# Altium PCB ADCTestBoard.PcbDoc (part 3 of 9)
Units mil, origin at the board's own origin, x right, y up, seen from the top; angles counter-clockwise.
Board outline 11022.62 x 9187 mil, 8 copper layers (TopLayer, InternalPlane1, InternalPlane2, InternalPlane3, InternalPlane4, InternalPlane5, MidLayer1, BottomLayer), stack 103.8 mil thick; 1282 components, 637 nets, 4473 pads, 1306 vias.
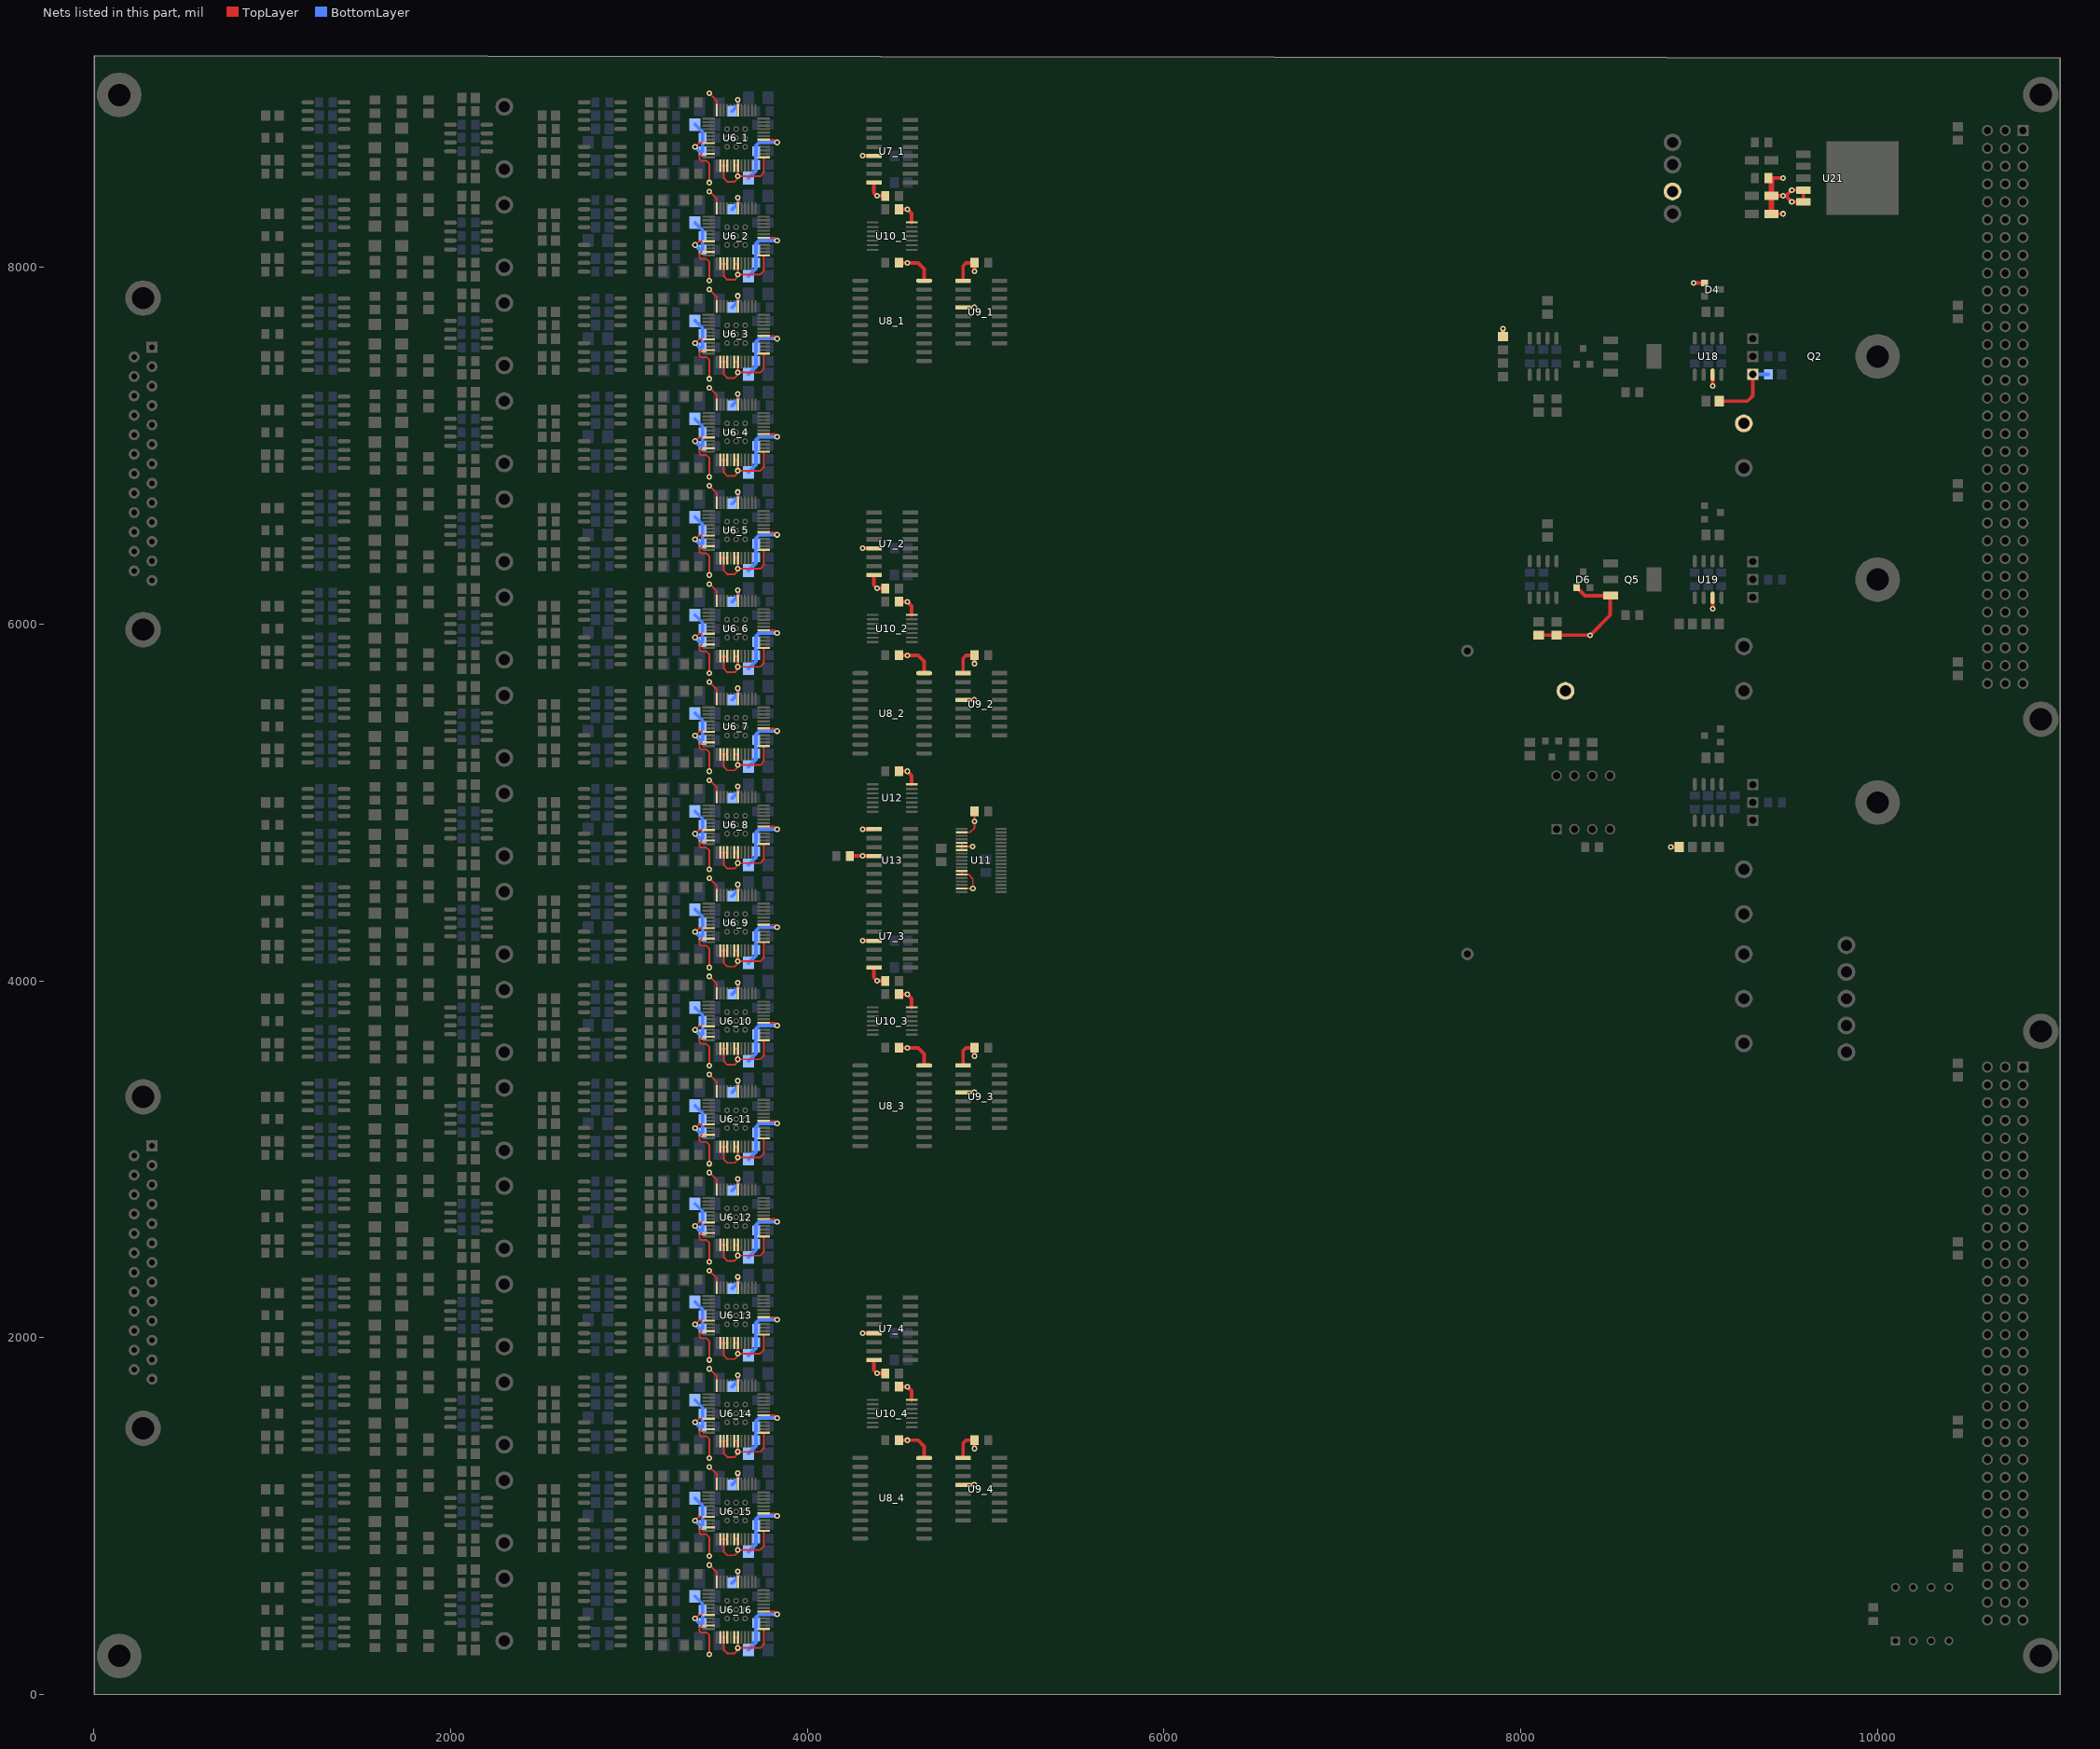
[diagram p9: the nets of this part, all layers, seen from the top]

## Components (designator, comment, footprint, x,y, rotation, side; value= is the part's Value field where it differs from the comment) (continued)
U3_10 "AD829JR" R-8D_N 2100,3775 r0 top (schematic designator U3)
U3_11 "AD829JR" R-8D_N 2100,3225 r0 top (schematic designator U3)
U3_12 "AD829JR" R-8D_N 2100,2675 r0 top (schematic designator U3)
U3_13 "AD829JR" R-8D_N 2100,2125 r0 top (schematic designator U3)
U3_14 "AD829JR" R-8D_N 2100,1575 r0 top (schematic designator U3)
U3_15 "AD829JR" R-8D_N 2100,1025 r0 top (schematic designator U3)
U3_16 "AD829JR" R-8D_N 2100,475 r0 top (schematic designator U3)
U4_1 "AD829JR" R-8D_N 2850,8600 r0 top (schematic designator U4)
U4_2 "AD829JR" R-8D_N 2850,8050 r0 top (schematic designator U4)
U4_3 "AD829JR" R-8D_N 2850,7500 r0 top (schematic designator U4)
U4_4 "AD829JR" R-8D_N 2850,6950 r0 top (schematic designator U4)
U4_5 "AD829JR" R-8D_N 2850,6400 r0 top (schematic designator U4)
U4_6 "AD829JR" R-8D_N 2850,5850 r0 top (schematic designator U4)
U4_7 "AD829JR" R-8D_N 2850,5300 r0 top (schematic designator U4)
U4_8 "AD829JR" R-8D_N 2850,4750 r0 top (schematic designator U4)
U4_9 "AD829JR" R-8D_N 2850,4200 r0 top (schematic designator U4)
U4_10 "AD829JR" R-8D_N 2850,3650 r0 top (schematic designator U4)
U4_11 "AD829JR" R-8D_N 2850,3100 r0 top (schematic designator U4)
U4_12 "AD829JR" R-8D_N 2850,2550 r0 top (schematic designator U4)
U4_13 "AD829JR" R-8D_N 2850,2000 r0 top (schematic designator U4)
U4_14 "AD829JR" R-8D_N 2850,1450 r0 top (schematic designator U4)
U4_15 "AD829JR" R-8D_N 2850,900 r0 top (schematic designator U4)
U4_16 "AD829JR" R-8D_N 2850,350 r0 top (schematic designator U4)
U5_1 "AD829JR" R-8D_N 2850,8850 r0 top (schematic designator U5)
U5_2 "AD829JR" R-8D_N 2850,8300 r0 top (schematic designator U5)
U5_3 "AD829JR" R-8D_N 2850,7750 r0 top (schematic designator U5)
U5_4 "AD829JR" R-8D_N 2850,7200 r0 top (schematic designator U5)
U5_5 "AD829JR" R-8D_N 2850,6650 r0 top (schematic designator U5)
U5_6 "AD829JR" R-8D_N 2850,6100 r0 top (schematic designator U5)
U5_7 "AD829JR" R-8D_N 2850,5550 r0 top (schematic designator U5)
U5_8 "AD829JR" R-8D_N 2850,5000 r0 top (schematic designator U5)
U5_9 "AD829JR" R-8D_N 2850,4450 r0 top (schematic designator U5)
U5_10 "AD829JR" R-8D_N 2850,3900 r0 top (schematic designator U5)
U5_11 "AD829JR" R-8D_N 2850,3350 r0 top (schematic designator U5)
U5_12 "AD829JR" R-8D_N 2850,2800 r0 top (schematic designator U5)
U5_13 "AD829JR" R-8D_N 2850,2250 r0 top (schematic designator U5)
U5_14 "AD829JR" R-8D_N 2850,1700 r0 top (schematic designator U5)
U5_15 "AD829JR" R-8D_N 2850,1150 r0 top (schematic designator U5)
U5_16 "AD829JR" R-8D_N 2850,600 r0 top (schematic designator U5)
U6_1 "AD7634" LFCSP_VQ48 3600,8725 r0 top (schematic designator U6)
U6_2 "AD7634" LFCSP_VQ48 3600,8175 r0 top (schematic designator U6)
U6_3 "AD7634" LFCSP_VQ48 3600,7625 r0 top (schematic designator U6)
U6_4 "AD7634" LFCSP_VQ48 3600,7075 r0 top (schematic designator U6)
U6_5 "AD7634" LFCSP_VQ48 3600,6525 r0 top (schematic designator U6)
U6_6 "AD7634" LFCSP_VQ48 3600,5975 r0 top (schematic designator U6)
U6_7 "AD7634" LFCSP_VQ48 3600,5425 r0 top (schematic designator U6)
U6_8 "AD7634" LFCSP_VQ48 3600,4875 r0 top (schematic designator U6)
U6_9 "AD7634" LFCSP_VQ48 3600,4325 r0 top (schematic designator U6)
U6_10 "AD7634" LFCSP_VQ48 3600,3775 r0 top (schematic designator U6)
U6_11 "AD7634" LFCSP_VQ48 3600,3225 r0 top (schematic designator U6)
U6_12 "AD7634" LFCSP_VQ48 3600,2675 r0 top (schematic designator U6)
U6_13 "AD7634" LFCSP_VQ48 3600,2125 r0 top (schematic designator U6)
U6_14 "AD7634" LFCSP_VQ48 3600,1575 r0 top (schematic designator U6)
U6_15 "AD7634" LFCSP_VQ48 3600,1025 r0 top (schematic designator U6)
U6_16 "AD7634" LFCSP_VQ48 3600,475 r0 top (schematic designator U6)
U7_1 "SN65LVDS048A" SO-G16 4475,8650 r90 top (schematic designator U7)
U7_2 "SN65LVDS048A" SO-G16 4475,6450 r90 top (schematic designator U7)
U7_3 "SN65LVDS048A" SO-G16 4475,4250 r90 top (schematic designator U7)
U7_4 "SN65LVDS048A" SO-G16 4475,2050 r90 top (schematic designator U7)
U8_1 "SN74LVC574ADWR" DW020_N 4475,7700 r0 top (schematic designator U8)
U8_2 "SN74LVC574ADWR" DW020_N 4475,5500 r0 top (schematic designator U8)
U8_3 "SN74LVC574ADWR" DW020_N 4475,3300 r0 top (schematic designator U8)
U8_4 "SN74LVC574ADWR" DW020_N 4475,1100 r0 top (schematic designator U8)
U9_1 "SN65LVDS047" SO-G16 4975,7750 r270 top (schematic designator U9)
U9_2 "SN65LVDS047" SO-G16 4975,5550 r270 top (schematic designator U9)
U9_3 "SN65LVDS047" SO-G16 4975,3350 r270 top (schematic designator U9)
U9_4 "SN65LVDS047" SO-G16 4975,1150 r270 top (schematic designator U9)
U10_1 "SN74LVC32APWR" PW014 4475,8175 r270 top (schematic designator U10)
U10_2 "SN74LVC32APWR" PW014 4475,5975 r270 top (schematic designator U10)
U10_3 "SN74LVC32APWR" PW014 4475,3775 r270 top (schematic designator U10)
U10_4 "SN74LVC32APWR" PW014 4475,1575 r270 top (schematic designator U10)
U11 "SN65LVDS109" TSSO10x6-G38 4975,4675 r270 top
U12 "SN74LVC32APWR" PW014 4475,5025 r270 top
U13 "SN65LVDS047" SO-G16 4475,4675 r270 top
U14 "25LC256P" DIP8 10100,300 r90 top
U15 "AD829JR" R-8D_N 8125,7500 r90 top
U16 "OP27GS" R-8D_N 8125,6250 r90 top
U17 "LT1021-5" N8 8350,5000 r0 top
U18 "AD829JR" R-8D_N 9050,7500 r90 top
U19 "AD829JR" R-8D_N 9050,6250 r90 top
U20 "AD829JR" R-8D_N 9050,5000 r90 top
U21 "LT1963EQ-3.3" TO-263 9750,8500 r270 top

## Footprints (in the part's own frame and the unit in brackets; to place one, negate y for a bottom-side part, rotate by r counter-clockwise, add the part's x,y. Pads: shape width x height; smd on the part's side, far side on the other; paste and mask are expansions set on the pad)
AXIAL1.7 [mil]
  round 70 hole 40: 1(-850,0) 2(850,0)
  silkscreen extent -780,-275 780,275
CC2013-0805 [mm] "Chip Capacitor; Body 2.0 x 1.3 mm (LxW typ)"
  rect 1.15x1.4 smd: 1(-0.975,0) 2(0.975,0)
  silkscreen extent -1.85,-0.6 -1.85,0.6
CC3216-1206 [mm] "Chip Capacitor; Body 3.2 x 1.6 mm (LxW typ)"
  rect 1.6x1.8 smd: 1(-1.4,0) 2(1.4,0)
  silkscreen extent -0.3,-0.8 0.3,0.8
CC3225-1210 [mm] "Chip Capacitor; Body 3.2 x 2.5 mm (LxW typ)"
  rect 1.6x2.7 smd: 1(-1.4,0) 2(1.4,0)
  silkscreen extent -0.3,-1.25 0.3,1.25
CR2012-0805 [mm] "Chip Resistor; Body 2.0 x 1.3 mm (LxW typ)"
  rect 1.3x1.5 smd: 1(-0.95,0) 2(0.95,0)
DB25RA/M [mil]
  round 200 hole 125: 0(-1583,50) 0(275,50)
  rect 62x62 hole 32: 1(0,0)
  round 62 hole 32: 2(-109,0) 3(-218,0) 4(-327,0) 5(-436,0) 6(-545,0) 7(-654,0) 8(-763,0) 9(-872,0) 10(-981,0) 11(-1090,0) 12(-1199,0) 13(-1308,0) 14(-55,100) 15(-164,100) 16(-273,100) 17(-382,100) 18(-491,100) 19(-600,100) 20(-709,100) 21(-818,100) 22(-927,100) 23(-1036,100) 24(-1145,100) 25(-1254,100)
  silkscreen extent -1708,-75 400,425
DIN96RA [mil]
  round 200 hole 125: 0(100,-3300) 0(100,200)
  rect 62x62 hole 40: 1A(0,0)
  round 62 hole 40: 1B(-100,0) 1C(-200,0) 2A(0,-100) 2B(-100,-100) 2C(-200,-100) 3A(0,-200) 3B(-100,-200) 3C(-200,-200) 4A(0,-300) 4B(-100,-300) 4C(-200,-300) 5A(0,-400) 5B(-100,-400) 5C(-200,-400) 6A(0,-500) 6B(-100,-500) 6C(-200,-500) 7A(0,-600) 7B(-100,-600) 7C(-200,-600) 8A(0,-700) 8B(-100,-700) 8C(-200,-700) 9A(0,-800) 9B(-100,-800) 9C(-200,-800) 10A(0,-900) 10B(-100,-900) 10C(-200,-900) 11A(0,-1000) 11B(-100,-1000) 11C(-200,-1000) 12A(0,-1100) 12B(-100,-1100) 12C(-200,-1100) 13A(0,-1200) 13B(-100,-1200) 13C(-200,-1200) 14A(0,-1300) 14B(-100,-1300) 14C(-200,-1300) 15A(0,-1400) 15B(-100,-1400) 15C(-200,-1400) 16A(0,-1500) 16B(-100,-1500) 16C(-200,-1500) 17A(0,-1600) 17B(-100,-1600) 17C(-200,-1600) 18A(0,-1700) 18B(-100,-1700) 18C(-200,-1700) 19A(0,-1800) 19B(-100,-1800) 19C(-200,-1800) 20A(0,-1900) 20B(-100,-1900) 20C(-200,-1900) 21A(0,-2000) 21B(-100,-2000) 21C(-200,-2000) 22A(0,-2100) 22B(-100,-2100) 22C(-200,-2100) 23A(0,-2200) 23B(-100,-2200) 23C(-200,-2200) 24A(0,-2300) 24B(-100,-2300) 24C(-200,-2300) 25A(0,-2400) 25B(-100,-2400) 25C(-200,-2400) 26A(0,-2500) 26B(-100,-2500) 26C(-200,-2500) 27A(0,-2600) 27B(-100,-2600) 27C(-200,-2600) 28A(0,-2700) 28B(-100,-2700) 28C(-200,-2700) 29A(0,-2800) 29B(-100,-2800) 29C(-200,-2800) 30A(0,-2900) 30B(-100,-2900) 30C(-200,-2900) 31A(0,-3000) 31B(-100,-3000) 31C(-200,-3000) 32A(0,-3100) 32B(-100,-3100) 32C(-200,-3100)
  silkscreen extent -250,-3400 200,300
DIP8 [mil]
  rect 50x50 hole 32: 1(0,0)
  round 50 hole 32: 2(0,-100) 3(0,-200) 4(0,-300) 5(300,-300) 6(300,-200) 7(300,-100) 8(300,0)
  silkscreen extent 50,-350 250,50
DW020_N [mm] "SOIC, 20-Leads, Body 12.8x7.5mm, Pitch 1.27mm, IPC Medium Density"
  oval 2.3x0.6 smd: 1(-4.55,5.715) 2(-4.55,4.445) 3(-4.55,3.175) 4(-4.55,1.905) 5(-4.55,0.635) 6(-4.55,-0.635) 7(-4.55,-1.905) 8(-4.55,-3.175) 9(-4.55,-4.445) 10(-4.55,-5.715) 11(4.55,-5.715) 12(4.55,-4.445) 13(4.55,-3.175) 14(4.55,-1.905) 15(4.55,-0.635) 16(4.55,0.635) 17(4.55,1.905) 18(4.55,3.175) 19(4.55,4.445) 20(4.55,5.715)
  silkscreen extent -4.67,-6.5 3,6.69, body extent -3.75,-6.4 3.75,6.4, height 2.65
LFCSP_VQ48 [mil]
  rect 11.81x70 smd: 1(-108.27,-155) 2(-88.58,-155) 3(-68.9,-155) 4(-49.21,-155) 5(-29.53,-155) 6(-9.84,-155) 7(9.84,-155) 8(29.53,-155) 9(49.21,-155) 10(68.9,-155) 11(88.58,-155) 12(108.27,-155) 25(108.27,155) 26(88.58,155) 27(68.9,155) 28(49.21,155) 29(29.53,155) 30(9.84,155) 31(-9.84,155) 32(-29.53,155) 33(-49.21,155) 34(-68.9,155) 35(-88.58,155) 36(-108.27,155)
  rect 70x11.81 smd: 13(155,-108.27) 14(155,-88.58) 15(155,-68.9) 16(155,-49.21) 17(155,-29.53) 18(155,-9.84) 19(155,9.84) 20(155,29.53) 21(155,49.21) 22(155,68.9) 23(155,88.58) 24(155,108.27) 37(-155,108.27) 38(-155,88.58) 39(-155,68.9) 40(-155,49.21) 41(-155,29.53) 42(-155,9.84) 43(-155,-9.84) 44(-155,-29.53) 45(-155,-49.21) 46(-155,-68.9) 47(-155,-88.58) 48(-155,-108.27)
  TopLayer region: -103.35,-103.35 103.35,-103.35 103.35,103.35 -103.35,103.35
  silkscreen extent -141,-169 110,110
N8 [mm] "DIP, Plastic; 8 Leads; Row Spacing 7.62 mm; Pitch 2.54 mm"
  rect 1.5x1.5 hole 1.016: 1(-3.81,-3.81)
  round 1.5 hole 1.016: 2(-1.27,-3.81) 3(1.27,-3.81) 4(3.81,-3.81) 5(3.81,3.81) 6(1.27,3.81) 7(-1.27,3.81) 8(-3.81,3.81)
  silkscreen extent -5.15,-2.65 5.15,2.65
PW014 [mm] "Shrink Small Outline; 14 Leads; Body Width 4.4 mm; Pitch 0.65 mm"
  rect 0.3x1.65 smd: 1(-1.95,-2.775) 2(-1.3,-2.775) 3(-0.65,-2.775) 4(0,-2.775) 5(0.65,-2.775) 6(1.3,-2.775) 7(1.95,-2.775) 8(1.95,2.775) 9(1.3,2.775) 10(0.65,2.775) 11(0,2.775) 12(-0.65,2.775) 13(-1.3,2.775) 14(-1.95,2.775)
  silkscreen extent -2.77,-2.9 2.55,1.55
R-8D_N [mm] "SOIC, 8-Leads, Body 4.9x3.9mm, Pitch 1.27mm, IPC Medium Density"
  oval 1.8x0.6 smd: 1(-2.6,1.905) 2(-2.6,0.635) 3(-2.6,-0.635) 4(-2.6,-1.905) 5(2.6,-1.905) 6(2.6,-0.635) 7(2.6,0.635) 8(2.6,1.905)
  silkscreen extent -2.72,-2.5 1.3,2.88, body extent -2,-2.5 2,2.5, height 2.59
SO-G3/C2.25 [mm] "SOT-23; 3 Leads; Body 3.0 x 2.5 mm, inc. leads (LxW max)"
  rect 0.95x1 smd: 1(-0.95,-1.125) 2(0.95,-1.125) 3(0,1.125)
  silkscreen extent -2.1,-1.25 1.32,1.13
SO-G16 [mm] "Small Outline; 16 Leads; Body Width 4 mm; Pitch 1.27 mm"
  rect 0.6x2.2 smd: 1(-4.445,-2.6) 2(-3.175,-2.6) 3(-1.905,-2.6) 4(-0.635,-2.6) 5(0.635,-2.6) 6(1.905,-2.6) 7(3.175,-2.6) 8(4.445,-2.6) 9(4.445,2.6) 10(3.175,2.6) 11(1.905,2.6) 12(0.635,2.6) 13(-0.635,2.6) 14(-1.905,2.6) 15(-3.175,2.6) 16(-4.445,2.6)
  silkscreen extent -5.42,-2.72 5,1.1
SOT223 [mm] "SOT-223/SC-73; 4 Leads; Body 6.7 x 7.3 mm, inc. leads (LxW max)"
  rect 1.1x2.15 smd: 1(-2.3,-3.1) 2(0,-3.1) 3(2.3,-3.1)
  rect 3.5x2.15 smd: 4(0,3.1)
  silkscreen extent -3.35,-4.85 3.35,1.63
TC3216-1206 [mm] "Capacitor, A Size, Tantalum; Body 3.2 x 1.6 mm (LxW typ)"
  rect 2x1.2 smd: 1(-1.4,0) 2(1.4,0)
  silkscreen extent -2.53,-0.9 1.7,1.12
TO-220H+HS [mil] "TO220 Package with surround for heatsink"
  round 250 hole 125: 0(0,0)
  rect 62x62 hole 40: 1(-100,-700) 2(0,-700) 3(100,-700)
  silkscreen extent -500,-640 500,240
TO-263 [mm] "D2-PAK; 5 Leads; Body 14.4 (inc. leads) x 10.4 mm (LxW max)"
  rect 1.05x2.1 smd: 1(-3.4,-4.225) 2(-1.7,-4.225) 3(0,-4.225) 4(1.7,-4.225) 5(3.4,-4.225)
  rect 10.5x10.3 smd: 6(0,4.225)
  silkscreen extent -5.55,-5.85 5.55,9.28
TP1 [mm] "Testpoint pin"
  round 2.54 hole 1.58: 1(0,0)
TSSO10x6-G38 [mm] "Shrink Small Outline; 38 Leads; Body Width 4.4 mm; Pitch 0.5 mm"
  rect 0.3x1.6 smd: 1(-4.5,-2.8) 2(-4,-2.8) 3(-3.5,-2.8) 4(-3,-2.8) 5(-2.5,-2.8) 6(-2,-2.8) 7(-1.5,-2.8) 8(-1,-2.8) 9(-0.5,-2.8) 10(0,-2.8) 11(0.5,-2.8) 12(1,-2.8) 13(1.5,-2.8) 14(2,-2.8) 15(2.5,-2.8) 16(3,-2.8) 17(3.5,-2.8) 18(4,-2.8) 19(4.5,-2.8) 20(4.5,2.8) 21(4,2.8) 22(3.5,2.8) 23(3,2.8) 24(2.5,2.8) 25(2,2.8) 26(1.5,2.8) 27(1,2.8) 28(0.5,2.8) 29(0,2.8) 30(-0.5,2.8) 31(-1,2.8) 32(-1.5,2.8) 33(-2,2.8) 34(-2.5,2.8) 35(-3,2.8) 36(-3.5,2.8) 37(-4,2.8) 38(-4.5,2.8)
  silkscreen extent -5.33,-2.92 4.9,1.6

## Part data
C1_1 C1_2 C1_3 C1_4 C1_5 C1_6 C1_7 C1_8 C1_9 C1_10 C1_11 C1_12 C1_13 C1_14 C1_15 C1_16 C2_1 C2_2 C2_3 C2_4 C2_5 C2_6 C2_7 C2_8 C2_9 C2_10 C2_11 C2_12 C2_13 C2_14 C2_15 C2_16 C3_1 C3_2 C3_3 C3_4 C3_5 C3_6 C3_7 C3_8 C3_9 C3_10 C3_11 C3_12 C3_13 C3_14 C3_15 C3_16 C4_1 C4_2 C4_3 C4_4 C4_5 C4_6 C4_7 C4_8 C4_9 C4_10 C4_11 C4_12 C4_13 C4_14 C4_15 C4_16 C5_1 C5_2 C5_3 C5_4 C5_5 C5_6 C5_7 C5_8 C5_9 C5_10 C5_11 C5_12 C5_13 C5_14 C5_15 C5_16 C6_1 C6_2 C6_3 C6_4 C6_5 C6_6 C6_7 C6_8 C6_9 C6_10 C6_11 C6_12 C6_13 C6_14 C6_15 C6_16 C7_1 C7_2 C7_3 C7_4 C7_5 C7_6 C7_7 C7_8 C7_9 C7_10 C7_11 C7_12 C7_13 C7_14 C7_15 C7_16 C8_1 C8_2 C8_3 C8_4 C8_5 C8_6 C8_7 C8_8 C8_9 C8_10 C8_11 C8_12 C8_13 C8_14 C8_15 C8_16 C9_1 C9_2 C9_3 C9_4 C9_5 C9_6 C9_7 C9_8 C9_9 C9_10 C9_11 C9_12 C9_13 C9_14 C9_15 C9_16 C10_1 C10_2 C10_3 C10_4 C10_5 C10_6 C10_7 C10_8 C10_9 C10_10 C10_11 C10_12 C10_13 C10_14 C10_15 C10_16 C11_1 C11_2 C11_3 C11_4 C11_5 C11_6 C11_7 C11_8 C11_9 C11_10 C11_11 C11_12 C11_13 C11_14 C11_15 C11_16 C12_1 C12_2 C12_3 C12_4 C12_5 C12_6 C12_7 C12_8 C12_9 C12_10 C12_11 C12_12 C12_13 C12_14 C12_15 C12_16 C13_1 C13_2 C13_3 C13_4 C13_5 C13_6 C13_7 C13_8 C13_9 C13_10 C13_11 C13_12 C13_13 C13_14 C13_15 C13_16 C14_1 C14_2 C14_3 C14_4 C14_5 C14_6 C14_7 C14_8 C14_9 C14_10 C14_11 C14_12 C14_13 C14_14 C14_15 C14_16 C15_1 C15_2 C15_3 C15_4 C15_5 C15_6 C15_7 C15_8 C15_9 C15_10 C15_11 C15_12 C15_13 C15_14 C15_15 C15_16 C16_1 C16_2 C16_3 C16_4 C16_5 C16_6 C16_7 C16_8 C16_9 C16_10 C16_11 C16_12 C16_13 C16_14 C16_15 C16_16 C17_1 C17_2 C17_3 C17_4 C17_5 C17_6 C17_7 C17_8 C17_9 C17_10 C17_11 C17_12 C17_13 C17_14 C17_15 C17_16 C18_1 C18_2 C18_3 C18_4 C18_5 C18_6 C18_7 C18_8 C18_9 C18_10 C18_11 C18_12 C18_13 C18_14 C18_15 C18_16 C19_1 C19_2 C19_3 C19_4 C19_5 C19_6 C19_7 C19_8 C19_9 C19_10 C19_11 C19_12 C19_13 C19_14 C19_15 C19_16 C20_1 C20_2 C20_3 C20_4 C20_5 C20_6 C20_7 C20_8 C20_9 C20_10 C20_11 C20_12 C20_13 C20_14 C20_15 C20_16 C21_1 C21_2 C21_3 C21_4 C21_5 C21_6 C21_7 C21_8 C21_9 C21_10 C21_11 C21_12 C21_13 C21_14 C21_15 C21_16 C22_1 C22_2 C22_3 C22_4 C22_5 C22_6 C22_7 C22_8 C22_9 C22_10 C22_11 C22_12 C22_13 C22_14 C22_15 C22_16 C23_1 C23_2 C23_3 C23_4 C23_5 C23_6 C23_7 C23_8 C23_9 C23_10 C23_11 C23_12 C23_13 C23_14 C23_15 C23_16 C24_1 C24_2 C24_3 C24_4 C24_5 C24_6 C24_7 C24_8 C24_9 C24_10 C24_11 C24_12 C24_13 C24_14 C24_15 C24_16 C25_1 C25_2 C25_3 C25_4 C25_5 C25_6 C25_7 C25_8 C25_9 C25_10 C25_11 C25_12 C25_13 C25_14 C25_15 C25_16 C26_1 C26_2 C26_3 C26_4 C26_5 C26_6 C26_7 C26_8 C26_9 C26_10 C26_11 C26_12 C26_13 C26_14 C26_15 C26_16 C27_1 C27_2 C27_3 C27_4 C27_5 C27_6 C27_7 C27_8 C27_9 C27_10 C27_11 C27_12 C27_13 C27_14 C27_15 C27_16 C28_1 C28_2 C28_3 C28_4 C28_5 C28_6 C28_7 C28_8 C28_9 C28_10 C28_11 C28_12 C28_13 C28_14 C28_15 C28_16 C29_1 C29_2 C29_3 C29_4 C29_5 C29_6 C29_7 C29_8 C29_9 C29_10 C29_11 C29_12 C29_13 C29_14 C29_15 C29_16 C30_1 C30_2 C30_3 C30_4 C30_5 C30_6 C30_7 C30_8 C30_9 C30_10 C30_11 C30_12 C30_13 C30_14 C30_15 C30_16 C32_1 C32_2 C32_3 C32_4 C32_5 C32_6 C32_7 C32_8 C32_9 C32_10 C32_11 C32_12 C32_13 C32_14 C32_15 C32_16 C33_1 C33_2 C33_3 C33_4 C33_5 C33_6 C33_7 C33_8 C33_9 C33_10 C33_11 C33_12 C33_13 C33_14 C33_15 C33_16 C34_1 C34_2 C34_3 C34_4 C34_5 C34_6 C34_7 C34_8 C34_9 C34_10 C34_11 C34_12 C34_13 C34_14 C34_15 C34_16 C36_1 C36_2 C36_3 C36_4 C36_5 C36_6 C36_7 C36_8 C36_9 C36_10 C36_11 C36_12 C36_13 C36_14 C36_15 C36_16 C37_1 C37_2 C37_3 C37_4 C37_5 C37_6 C37_7 C37_8 C37_9 C37_10 C37_11 C37_12 C37_13 C37_14 C37_15 C37_16 C38_1 C38_2 C38_3 C38_4 C38_5 C38_6 C38_7 C38_8 C38_9 C38_10 C38_11 C38_12 C38_13 C38_14 C38_15 C38_16 C39_1 C39_2 C39_3 C39_4 C39_5 C39_6 C39_7 C39_8 C39_9 C39_10 C39_11 C39_12 C39_13 C39_14 C39_15 C39_16 C40_1 C40_2 C40_3 C40_4 C40_5 C40_6 C40_7 C40_8 C40_9 C40_10 C40_11 C40_12 C40_13 C40_14 C40_15 C40_16 C41_1 C41_2 C41_3 C41_4 C41_5 C41_6 C41_7 C41_8 C41_9 C41_10 C41_11 C41_12 C41_13 C41_14 C41_15 C41_16 C42_1 C42_2 C42_3 C42_4 C42_5 C42_6 C42_7 C42_8 C42_9 C42_10 C42_11 C42_12 C42_13 C42_14 C42_15 C42_16 C43_1 C43_2 C43_3 C43_4 C44_1 C44_2 C44_3 C44_4 C45_1 C45_2 C45_3 C45_4 C46_1 C46_2 C46_3 C46_4 C82 C83 C84 C85: library part "Cap Semi", "Capacitor (Semiconductor SIM Model)"
C31_1 C31_2 C31_3 C31_4 C31_5 C31_6 C31_7 C31_8 C31_9 C31_10 C31_11 C31_12 C31_13 C31_14 C31_15 C31_16 C35_1 C35_2 C35_3 C35_4 C35_5 C35_6 C35_7 C35_8 C35_9 C35_10 C35_11 C35_12 C35_13 C35_14 C35_15 C35_16: library part T494D, "Solid Tantalum Chip Capacitor, Standard T494 Series - Low ESR, Industrial Grade"
C47 C48 C49 C50 C51 C52 C54 C55 C56 C57 C58 C59 C60 C61 C62 C63 C64 C65 C78 C79 C80 C81: library part ChipCap, "Capacitor, surface mount"
C53: library part PolyCap, "Polypropylene Film Capacitor, radial lead"
C75 C76 C77: library part ChipTantalum, "Tantalum capacitor, surface mount"
D1 D2 D3 D4 D5 D6: library part DIODE_SOT23, "Single diode in SOT23 package"
J1 J2: "Receptacle Assembly, 25 Position, Right Angle"
P1 P2: "DIN 96"
Q1 Q5: library part PZTA42, "NPN High-voltage Transistor"
Q2 Q3: library part D44H8, "NPN Power Amplifier"
Q4: library part D45H8, "PNP Power Amplifier"
R1_1 R1_2 R1_3 R1_4 R1_5 R1_6 R1_7 R1_8 R1_9 R1_10 R1_11 R1_12 R1_13 R1_14 R1_15 R1_16 R2_1 R2_2 R2_3 R2_4 R2_5 R2_6 R2_7 R2_8 R2_9 R2_10 R2_11 R2_12 R2_13 R2_14 R2_15 R2_16 R3_1 R3_2 R3_3 R3_4 R3_5 R3_6 R3_7 R3_8 R3_9 R3_10 R3_11 R3_12 R3_13 R3_14 R3_15 R3_16 R4_1 R4_2 R4_3 R4_4 R4_5 R4_6 R4_7 R4_8 R4_9 R4_10 R4_11 R4_12 R4_13 R4_14 R4_15 R4_16 R5_1 R5_2 R5_3 R5_4 R5_5 R5_6 R5_7 R5_8 R5_9 R5_10 R5_11 R5_12 R5_13 R5_14 R5_15 R5_16 R6_1 R6_2 R6_3 R6_4 R6_5 R6_6 R6_7 R6_8 R6_9 R6_10 R6_11 R6_12 R6_13 R6_14 R6_15 R6_16 R7_1 R7_2 R7_3 R7_4 R7_5 R7_6 R7_7 R7_8 R7_9 R7_10 R7_11 R7_12 R7_13 R7_14 R7_15 R7_16 R8_1 R8_2 R8_3 R8_4 R8_5 R8_6 R8_7 R8_8 R8_9 R8_10 R8_11 R8_12 R8_13 R8_14 R8_15 R8_16 R9_1 R9_2 R9_3 R9_4 R9_5 R9_6 R9_7 R9_8 R9_9 R9_10 R9_11 R9_12 R9_13 R9_14 R9_15 R9_16 R10_1 R10_2 R10_3 R10_4 R10_5 R10_6 R10_7 R10_8 R10_9 R10_10 R10_11 R10_12 R10_13 R10_14 R10_15 R10_16 R11_1 R11_2 R11_3 R11_4 R11_5 R11_6 R11_7 R11_8 R11_9 R11_10 R11_11 R11_12 R11_13 R11_14 R11_15 R11_16 R12_1 R12_2 R12_3 R12_4 R12_5 R12_6 R12_7 R12_8 R12_9 R12_10 R12_11 R12_12 R12_13 R12_14 R12_15 R12_16 R13_1 R13_2 R13_3 R13_4 R13_5 R13_6 R13_7 R13_8 R13_9 R13_10 R13_11 R13_12 R13_13 R13_14 R13_15 R13_16 R14_1 R14_2 R14_3 R14_4 R14_5 R14_6 R14_7 R14_8 R14_9 R14_10 R14_11 R14_12 R14_13 R14_14 R14_15 R14_16 R15_1 R15_2 R15_3 R15_4 R15_5 R15_6 R15_7 R15_8 R15_9 R15_10 R15_11 R15_12 R15_13 R15_14 R15_15 R15_16 R16_1 R16_2 R16_3 R16_4 R16_5 R16_6 R16_7 R16_8 R16_9 R16_10 R16_11 R16_12 R16_13 R16_14 R16_15 R16_16 R17_1 R17_2 R17_3 R17_4 R17_5 R17_6 R17_7 R17_8 R17_9 R17_10 R17_11 R17_12 R17_13 R17_14 R17_15 R17_16 R18_1 R18_2 R18_3 R18_4 R18_5 R18_6 R18_7 R18_8 R18_9 R18_10 R18_11 R18_12 R18_13 R18_14 R18_15 R18_16 R19_1 R19_2 R19_3 R19_4 R19_5 R19_6 R19_7 R19_8 R19_9 R19_10 R19_11 R19_12 R19_13 R19_14 R19_15 R19_16 R20_1 R20_2 R20_3 R20_4 R20_5 R20_6 R20_7 R20_8 R20_9 R20_10 R20_11 R20_12 R20_13 R20_14 R20_15 R20_16 R21_1 R21_2 R21_3 R21_4 R21_5 R21_6 R21_7 R21_8 R21_9 R21_10 R21_11 R21_12 R21_13 R21_14 R21_15 R21_16: library part Res2, "Resistor"
R22_1 R22_2 R22_3 R22_4 R23_1 R23_2 R23_3 R23_4 R24 R25: library part Res1, "Resistor"
R26 R27 R28 R29 R30 R31 R32 R33 R34 R35 R36 R37 R38 R39 R40 R41 R42 R43 R44 R45 R46 R47 R48 R49 R50 R51 R52 R53 R54: library part ChipRes2, "Resistor, surface mount"
TP1_1 TP1_2 TP1_3 TP1_4 TP1_5 TP1_6 TP1_7 TP1_8 TP1_9 TP1_10 TP1_11 TP1_12 TP1_13 TP1_14 TP1_15 TP1_16 TP3: library part TP_SIGNAL, "Testpoint, yellow"
TP2_1 TP2_2 TP2_3 TP2_4 TP2_5 TP2_6 TP2_7 TP2_8 TP2_9 TP2_10 TP2_11 TP2_12 TP2_13 TP2_14 TP2_15 TP2_16: library part TP_GND
TP4 TP5 TP10: library part TP_NEGATIVE, "Testpoint, white"
TP6 TP7 TP8 TP9 TP11 TP12 TP19: library part TP_POSITIVE, "Testpoint, red"
TP13 TP14 TP15 TP16 TP17 TP18 TP20 TP21: library part TP_GND, "Testpoint, black"
U1_1 U1_2 U1_3 U1_4 U1_5 U1_6 U1_7 U1_8 U1_9 U1_10 U1_11 U1_12 U1_13 U1_14 U1_15 U1_16 U2_1 U2_2 U2_3 U2_4 U2_5 U2_6 U2_7 U2_8 U2_9 U2_10 U2_11 U2_12 U2_13 U2_14 U2_15 U2_16 U3_1 U3_2 U3_3 U3_4 U3_5 U3_6 U3_7 U3_8 U3_9 U3_10 U3_11 U3_12 U3_13 U3_14 U3_15 U3_16 U4_1 U4_2 U4_3 U4_4 U4_5 U4_6 U4_7 U4_8 U4_9 U4_10 U4_11 U4_12 U4_13 U4_14 U4_15 U4_16 U5_1 U5_2 U5_3 U5_4 U5_5 U5_6 U5_7 U5_8 U5_9 U5_10 U5_11 U5_12 U5_13 U5_14 U5_15 U5_16 U15 U18 U19 U20: "High-Speed, Low-Noise Video Operational Amplifier"
U6_1 U6_2 U6_3 U6_4 U6_5 U6_6 U6_7 U6_8 U6_9 U6_10 U6_11 U6_12 U6_13 U6_14 U6_15 U6_16: library part AD7634BST, "18 bit SAR ADC, 670kSPS, 10V bipolar"
U7_1 U7_2 U7_3 U7_4: library part SN65LVDS048, "LVDS RCVR"
U8_1 U8_2 U8_3 U8_4: library part SN74LVC574SC, "Octal D type flip-flop"
U9_1 U9_2 U9_3 U9_4 U13: "LVDS DRIVER"
U10_1 U10_2 U10_3 U10_4 U12: library part SN74LVC32AD, "Quadruple 2-Input Positive-OR Gate"
U11: "Dual 4 Port LVDS Repeater"
U14: library part "256K Serial EEPROM", "256K Serial EEPROM"
U16: "Low-Noise, Precision Operational Amplifier"
U17: library part LT1021-7, "Voltage Ref"
U21: library part LT1764A, "5 Terminal positive LDO regulator"

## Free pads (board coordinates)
  round 32 hole 16: 0(3550,425) 0(3550,475) 0(3550,525) 0(3550,975) 0(3550,1025) 0(3550,1075) 0(3550,1525) 0(3550,1575) 0(3550,1625) 0(3550,2075) 0(3550,2125) 0(3550,2175) 0(3550,2625) 0(3550,2675) 0(3550,2725) 0(3550,3175) 0(3550,3225) 0(3550,3275) 0(3550,3725) 0(3550,3775) 0(3550,3825) 0(3550,4275) 0(3550,4325) 0(3550,4375) 0(3550,4825) 0(3550,4875) 0(3550,4925) 0(3550,5375) 0(3550,5425) 0(3550,5475) 0(3550,5925) 0(3550,5975) 0(3550,6025) 0(3550,6475) 0(3550,6525) 0(3550,6575) 0(3550,7025) 0(3550,7075) 0(3550,7125) 0(3550,7575) 0(3550,7625) 0(3550,7675) 0(3550,8125) 0(3550,8175) 0(3550,8225) 0(3550,8675) 0(3550,8725) 0(3550,8775) 0(3600,425) 0(3600,475) 0(3600,525) 0(3600,975) 0(3600,1025) 0(3600,1075) 0(3600,1525) 0(3600,1575) 0(3600,1625) 0(3600,2075) 0(3600,2125) 0(3600,2175) 0(3600,2625) 0(3600,2675) 0(3600,2725) 0(3600,3175) 0(3600,3225) 0(3600,3275) 0(3600,3725) 0(3600,3775) 0(3600,3825) 0(3600,4275) 0(3600,4325) 0(3600,4375) 0(3600,4825) 0(3600,4875) 0(3600,4925) 0(3600,5375) 0(3600,5425) 0(3600,5475) 0(3600,5925) 0(3600,5975) 0(3600,6025) 0(3600,6475) 0(3600,6525) 0(3600,6575) 0(3600,7025) 0(3600,7075) 0(3600,7125) 0(3600,7575) 0(3600,7625) 0(3600,7675) 0(3600,8125) 0(3600,8175) 0(3600,8225) 0(3600,8675) 0(3600,8725) 0(3600,8775) 0(3650,425) 0(3650,475) 0(3650,525) 0(3650,975) 0(3650,1025) 0(3650,1075) 0(3650,1525) 0(3650,1575) 0(3650,1625) 0(3650,2075) 0(3650,2125) 0(3650,2175) 0(3650,2625) 0(3650,2675) 0(3650,2725) 0(3650,3175) 0(3650,3225) 0(3650,3275) 0(3650,3725) 0(3650,3775) 0(3650,3825) 0(3650,4275) 0(3650,4325) 0(3650,4375) 0(3650,4825) 0(3650,4875) 0(3650,4925) 0(3650,5375) 0(3650,5425) 0(3650,5475) 0(3650,5925) 0(3650,5975) 0(3650,6025) 0(3650,6475) 0(3650,6525) 0(3650,6575) 0(3650,7025) 0(3650,7075) 0(3650,7125) 0(3650,7575) 0(3650,7625) 0(3650,7675) 0(3650,8125) 0(3650,8175) 0(3650,8225) 0(3650,8675) 0(3650,8725) 0(3650,8775)
  round 250 hole 125: 1(141,8966) 4(141,216)

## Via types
v1: diameter 32, hole 16, TopLayer to BottomLayer, 1306 vias

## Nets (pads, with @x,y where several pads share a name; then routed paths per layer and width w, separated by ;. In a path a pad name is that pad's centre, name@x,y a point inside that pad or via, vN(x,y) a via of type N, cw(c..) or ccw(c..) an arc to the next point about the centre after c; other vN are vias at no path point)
+3.3V: C23_1.2 C23_2.2 C23_3.2 C23_4.2 C23_5.2 C23_6.2 C23_7.2 C23_8.2 C23_9.2 C23_10.2 C23_11.2 C23_12.2 C23_13.2 C23_14.2 C23_15.2 C23_16.2 C24_1.2 C24_2.2 C24_3.2 C24_4.2 C24_5.2 C24_6.2 C24_7.2 C24_8.2 C24_9.2 C24_10.2 C24_11.2 C24_12.2 C24_13.2 C24_14.2 C24_15.2 C24_16.2 C25_1.2 C25_2.2 C25_3.2 C25_4.2 C25_5.2 C25_6.2 C25_7.2 C25_8.2 C25_9.2 C25_10.2 C25_11.2 C25_12.2 C25_13.2 C25_14.2 C25_15.2 C25_16.2 C43_1.1 C43_2.1 C43_3.1 C43_4.1 C44_1.1 C44_2.1 C44_3.1 C44_4.1 C45_1.1 C45_2.1 C45_3.1 C45_4.1 C46_1.1 C46_2.1 C46_3.1 C46_4.1 C76.1 C77.1 C79.2 C82.1 C83.1 C84.1 TP19.1 U6_1.18 U6_2.18 U6_3.18 U6_4.18 U6_5.18 U6_6.18 U6_7.18 U6_8.18 U6_9.18 U6_10.18 U6_11.18 U6_12.18 U6_13.18 U6_14.18 U6_15.18 U6_16.18 U7_1.13 U7_1.16 U7_2.13 U7_2.16 U7_3.13 U7_3.16 U7_4.13 U7_4.16 U8_1.20 U8_2.20 U8_3.20 U8_4.20 U9_1.1 U9_1.4 U9_2.1 U9_2.4 U9_3.1 U9_3.4 U9_4.1 U9_4.4 U10_1.14 U10_2.14 U10_3.14 U10_4.14 U11.2 U11.5 U11.6 U11.7 U11.13 U11.14 U11.18 U12.14 U13.1 U13.4 U21.4 U21.5 | length 11256.9
  TopLayer w10: U6_16.18@3755,465.16 3814.84,465.16 v1(3830,450) ; U6_15.18@3755,1015.16 3814.84,1015.16 v1(3830,1000) ; U6_14.18@3755,1565.16 3814.84,1565.16 v1(3830,1550) ; U6_13.18@3755,2115.16 3814.84,2115.16 v1(3830,2100) ; U6_12.18@3755,2665.16 3814.84,2665.16 v1(3830,2650) ; U6_11.18@3755,3215.16 3814.84,3215.16 v1(3830,3200) ; U6_10.18@3755,3765.16 3814.84,3765.16 v1(3830,3750) ; U6_9.18@3755,4315.16 3814.84,4315.16 v1(3830,4300) ; U6_8.18@3755,4865.16 3814.84,4865.16 v1(3830,4850) ; U6_7.18@3755,5415.16 3814.84,5415.16 v1(3830,5400) ; U6_6.18@3755,5965.16 3814.84,5965.16 v1(3830,5950) ; U6_5.18@3755,6515.16 3814.84,6515.16 v1(3830,6500) ; U6_4.18@3755,7065.16 3814.84,7065.16 v1(3830,7050) ; U6_3.18@3755,7615.16 3814.84,7615.16 v1(3830,7600) ; U6_2.18@3755,8165.16 3814.84,8165.16 v1(3830,8150) ; U6_1.18@3755,8715.16 3814.84,8715.16 v1(3830,8700) ; U11.18@4864.76,4517.52 v1(4927.52,4517.52) 4927.52,4572.48 4903.74,4596.26 U11.14@4864.76,4596.26 U11.13@4864.76,4615.94 ; U11.7@4864.76,4734.06 U11.5@4864.76,4773.43 ; U11.6@4864.76,4753.74 v1(4926.26,4753.74) ; U11.2@4864.76,4832.48 4912.48,4832.48 4936.61,4856.61 C82.1@4936.61,4950
  TopLayer w20: C84.1@4238.39,4700 U13.4@4372.64,4700 ; v1(4310,2025) U7_4.13@4372.64,2025 ; v1(4310,4225) U7_3.13@4372.64,4225 ; v1(4310,4850) U13.1@4372.64,4850 ; v1(4310,6425) U7_2.13@4372.64,6425 ; v1(4310,8625) U7_1.13@4372.64,8625 ; U7_4.16@4372.64,1875 4372.64,1817.36 v1(4390,1800) C43_4.1@4436.61,1800 ; U7_3.16@4372.64,4075 4372.64,4017.36 v1(4390,4000) C43_3.1@4436.61,4000 ; U7_2.16@4372.64,6275 4372.64,6217.36 v1(4390,6200) C43_2.1@4436.61,6200 ; U7_1.16@4372.64,8475 4372.64,8417.36 v1(4390,8400) C43_1.1@4436.61,8400 ; C44_4.1@4513.39,1425 4620,1425 4654.13,1390.87 U8_4.20@4654.13,1325 ; C46_4.1@4513.39,1725 v1(4560,1725) 4584.25,1700.75 U10_4.14@4584.25,1651.77 ; C44_3.1@4513.39,3625 4620,3625 4654.13,3590.87 U8_3.20@4654.13,3525 ; C46_3.1@4513.39,3925 v1(4560,3925) 4584.25,3900.75 U10_3.14@4584.25,3851.77 ; C83.1@4513.39,5175 v1(4560,5175) 4584.25,5150.75 U12.14@4584.25,5101.77 ; C44_2.1@4513.39,5825 4620,5825 4654.13,5790.87 U8_2.20@4654.13,5725 ; C46_2.1@4513.39,6125 v1(4560,6125) 4584.25,6100.75 U10_2.14@4584.25,6051.77 ; C44_1.1@4513.39,8025 4620,8025 4654.13,7990.87 U8_1.20@4654.13,7925 ; C46_1.1@4513.39,8325 v1(4560,8325) 4584.25,8300.75 U10_1.14@4584.25,8251.77 ; U9_4.4@4872.64,1175 v1(4935.28,1175) ; U9_4.1@4872.64,1325 4872.64,1407.64 4890,1425 C45_4.1@4936.61,1425 v1(4936.61,1378.39) ; U9_3.4@4872.64,3375 v1(4935.28,3375) ; U9_3.1@4872.64,3525 4872.64,3607.64 4890,3625 C45_3.1@4936.61,3625 v1(4936.61,3578.39) ; U9_2.4@4872.64,5575 v1(4935.28,5575) ; U9_2.1@4872.64,5725 4872.64,5807.64 4890,5825 C45_2.1@4936.61,5825 v1(4936.61,5778.39) ; U9_1.4@4872.64,7775 v1(4935.28,7775) ; U9_1.1@4872.64,7925 4872.64,8007.64 4890,8025 C45_1.1@4936.61,8025 v1(4936.61,7978.39) ; C79.2@9388.39,8500 v1(9470,8500) ; C77.1@9405.12,8300 v1(9470,8300) ; C76.1@9405.12,8400 9484.92,8400 v1(9518.78,8366.14) U21.5@9583.66,8366.14 U21.4@9583.66,8433.07 v1(9518.78,8433.07) v1@9485.71,8400
  TopLayer w30: C79.2@9388.39,8500 9405.12,8483.27 C77.1@9405.12,8300
  BottomLayer w20: C25_16.2@3669.88,250 3711.61,291.73 3711.61,431.61 3730,450 v1(3830,450) ; C25_15.2@3669.88,800 3711.61,841.73 3711.61,981.61 3730,1000 v1(3830,1000) ; C25_14.2@3669.88,1350 3711.61,1391.73 3711.61,1531.61 3730,1550 v1(3830,1550) ; C25_13.2@3669.88,1900 3711.61,1941.73 3711.61,2081.61 3730,2100 v1(3830,2100) ; C25_12.2@3669.88,2450 3711.61,2491.73 3711.61,2631.61 3730,2650 v1(3830,2650) ; C25_11.2@3669.88,3000 3711.61,3041.73 3711.61,3181.61 3730,3200 v1(3830,3200) ; C25_10.2@3669.88,3550 3711.61,3591.73 3711.61,3731.61 3730,3750 v1(3830,3750) ; C25_9.2@3669.88,4100 3711.61,4141.73 3711.61,4281.61 3730,4300 v1(3830,4300) ; C25_8.2@3669.88,4650 3711.61,4691.73 3711.61,4831.61 3730,4850 v1(3830,4850) ; C25_7.2@3669.88,5200 3711.61,5241.73 3711.61,5381.61 3730,5400 v1(3830,5400) ; C25_6.2@3669.88,5750 3711.61,5791.73 3711.61,5931.61 3730,5950 v1(3830,5950) ; C25_5.2@3669.88,6300 3711.61,6341.73 3711.61,6481.61 3730,6500 v1(3830,6500) ; C25_4.2@3669.88,6850 3711.61,6891.73 3711.61,7031.61 3730,7050 v1(3830,7050) ; C25_3.2@3669.88,7400 3711.61,7441.73 3711.61,7581.61 3730,7600 v1(3830,7600) ; C25_2.2@3669.88,7950 3711.61,7991.73 3711.61,8131.61 3730,8150 v1(3830,8150) ; C25_1.2@3669.88,8500 3711.61,8541.73 3711.61,8681.61 3730,8700 v1(3830,8700)
  other v1: 4560,1425 4560,3625 4310,4700 4936.61,4893.39 4560,5825 4560,8025 9470,8400
+5V: C13_1.2 C13_2.2 C13_3.2 C13_4.2 C13_5.2 C13_6.2 C13_7.2 C13_8.2 C13_9.2 C13_10.2 C13_11.2 C13_12.2 C13_13.2 C13_14.2 C13_15.2 C13_16.2 C14_1.2 C14_2.2 C14_3.2 C14_4.2 C14_5.2 C14_6.2 C14_7.2 C14_8.2 C14_9.2 C14_10.2 C14_11.2 C14_12.2 C14_13.2 C14_14.2 C14_15.2 C14_16.2 C15_1.2 C15_2.2 C15_3.2 C15_4.2 C15_5.2 C15_6.2 C15_7.2 C15_8.2 C15_9.2 C15_10.2 C15_11.2 C15_12.2 C15_13.2 C15_14.2 C15_15.2 C15_16.2 D4.1 Q2.3 R8_1.2 R8_2.2 R8_3.2 R8_4.2 R8_5.2 R8_6.2 R8_7.2 R8_8.2 R8_9.2 R8_10.2 R8_11.2 R8_12.2 R8_13.2 R8_14.2 R8_15.2 R8_16.2 R39.2 R43.1 TP11.1 U6_1.2 U6_1.3 U6_1.4 U6_1.6 U6_1.7 U6_1.13 U6_1.30 U6_1.36 U6_1.44 U6_1.47 U6_2.2 U6_2.3 U6_2.4 U6_2.6 U6_2.7 U6_2.13 U6_2.30 U6_2.36 U6_2.44 U6_2.47 U6_3.2 U6_3.3 U6_3.4 U6_3.6 U6_3.7 U6_3.13 U6_3.30 U6_3.36 U6_3.44 U6_3.47 U6_4.2 U6_4.3 U6_4.4 U6_4.6 U6_4.7 U6_4.13 U6_4.30 U6_4.36 U6_4.44 U6_4.47 U6_5.2 U6_5.3 U6_5.4 U6_5.6 U6_5.7 U6_5.13 U6_5.30 U6_5.36 U6_5.44 U6_5.47 U6_6.2 U6_6.3 U6_6.4 U6_6.6 U6_6.7 U6_6.13 U6_6.30 U6_6.36 U6_6.44 U6_6.47 U6_7.2 U6_7.3 U6_7.4 U6_7.6 U6_7.7 U6_7.13 U6_7.30 U6_7.36 U6_7.44 U6_7.47 U6_8.2 U6_8.3 U6_8.4 U6_8.6 U6_8.7 U6_8.13 U6_8.30 U6_8.36 U6_8.44 U6_8.47 U6_9.2 U6_9.3 U6_9.4 U6_9.6 U6_9.7 U6_9.13 U6_9.30 U6_9.36 U6_9.44 U6_9.47 U6_10.2 U6_10.3 U6_10.4 U6_10.6 U6_10.7 U6_10.13 U6_10.30 U6_10.36 U6_10.44 U6_10.47 U6_11.2 U6_11.3 U6_11.4 U6_11.6 U6_11.7 U6_11.13 U6_11.30 U6_11.36 U6_11.44 U6_11.47 U6_12.2 U6_12.3 U6_12.4 U6_12.6 U6_12.7 U6_12.13 U6_12.30 U6_12.36 U6_12.44 U6_12.47 U6_13.2 U6_13.3 U6_13.4 U6_13.6 U6_13.7 U6_13.13 U6_13.30 U6_13.36 U6_13.44 U6_13.47 U6_14.2 U6_14.3 U6_14.4 U6_14.6 U6_14.7 U6_14.13 U6_14.30 U6_14.36 U6_14.44 U6_14.47 U6_15.2 U6_15.3 U6_15.4 U6_15.6 U6_15.7 U6_15.13 U6_15.30 U6_15.36 U6_15.44 U6_15.47 U6_16.2 U6_16.3 U6_16.4 U6_16.6 U6_16.7 U6_16.13 U6_16.30 U6_16.36 U6_16.44 U6_16.47 | length 21816.4
  TopLayer w10: v1(3370,425) 3390.47,445.47 U6_16.44@3445,445.47 ; v1(3370,975) 3390.47,995.47 U6_15.44@3445,995.47 ; v1(3370,1525) 3390.47,1545.47 U6_14.44@3445,1545.47 ; v1(3370,2075) 3390.47,2095.47 U6_13.44@3445,2095.47 ; v1(3370,2625) 3390.47,2645.47 U6_12.44@3445,2645.47 ; v1(3370,3175) 3390.47,3195.47 U6_11.44@3445,3195.47 ; v1(3370,3725) 3390.47,3745.47 U6_10.44@3445,3745.47 ; v1(3370,4275) 3390.47,4295.47 U6_9.44@3445,4295.47 ; v1(3370,4825) 3390.47,4845.47 U6_8.44@3445,4845.47 ; v1(3370,5375) 3390.47,5395.47 U6_7.44@3445,5395.47 ; v1(3370,5925) 3390.47,5945.47 U6_6.44@3445,5945.47 ; v1(3370,6475) 3390.47,6495.47 U6_5.44@3445,6495.47 ; v1(3370,7025) 3390.47,7045.47 U6_4.44@3445,7045.47 ; v1(3370,7575) 3390.47,7595.47 U6_3.44@3445,7595.47 ; v1(3370,8125) 3390.47,8145.47 U6_2.44@3445,8145.47 ; v1(3370,8675) 3390.47,8695.47 U6_1.44@3445,8695.47 ; U6_16.47@3445,386.42 3406.42,386.42 3395,375 3395,355 3402.34,347.66 3432.34,347.66 3450,330 v1(3450,225) ; U6_15.47@3445,936.42 3406.42,936.42 3395,925 3395,905 3402.34,897.66 3432.34,897.66 3450,880 v1(3450,775) ; U6_14.47@3445,1486.42 3406.42,1486.42 3395,1475 3395,1455 3402.34,1447.66 3432.34,1447.66 3450,1430 v1(3450,1325) ; U6_13.47@3445,2036.42 3406.42,2036.42 3395,2025 3395,2005 3402.34,1997.66 3432.34,1997.66 3450,1980 v1(3450,1875) ; U6_12.47@3445,2586.42 3406.42,2586.42 3395,2575 3395,2555 3402.34,2547.66 3432.34,2547.66 3450,2530 v1(3450,2425) ; U6_11.47@3445,3136.42 3406.42,3136.42 3395,3125 3395,3105 3402.34,3097.66 3432.34,3097.66 3450,3080 v1(3450,2975) ; U6_10.47@3445,3686.42 3406.42,3686.42 3395,3675 3395,3655 3402.34,3647.66 3432.34,3647.66 3450,3630 v1(3450,3525) ; U6_9.47@3445,4236.42 3406.42,4236.42 3395,4225 3395,4205 3402.34,4197.66 3432.34,4197.66 3450,4180 v1(3450,4075) ; U6_8.47@3445,4786.42 3406.42,4786.42 3395,4775 3395,4755 3402.34,4747.66 3432.34,4747.66 3450,4730 v1(3450,4625) ; U6_7.47@3445,5336.42 3406.42,5336.42 3395,5325 3395,5305 3402.34,5297.66 3432.34,5297.66 3450,5280 v1(3450,5175) ; U6_6.47@3445,5886.42 3406.42,5886.42 3395,5875 3395,5855 3402.34,5847.66 3432.34,5847.66 3450,5830 v1(3450,5725) ; U6_5.47@3445,6436.42 3406.42,6436.42 3395,6425 3395,6405 3402.34,6397.66 3432.34,6397.66 3450,6380 v1(3450,6275) ; U6_4.47@3445,6986.42 3406.42,6986.42 3395,6975 3395,6955 3402.34,6947.66 3432.34,6947.66 3450,6930 v1(3450,6825) ; U6_3.47@3445,7536.42 3406.42,7536.42 3395,7525 3395,7505 3402.34,7497.66 3432.34,7497.66 3450,7480 v1(3450,7375) ; U6_2.47@3445,8086.42 3406.42,8086.42 3395,8075 3395,8055 3402.34,8047.66 3432.34,8047.66 3450,8030 v1(3450,7925) ; U6_1.47@3445,8636.42 3406.42,8636.42 3395,8625 3395,8605 3402.34,8597.66 3432.34,8597.66 3450,8580 v1(3450,8475) ; v1(3450,725) 3491.73,683.27 U6_16.36@3491.73,630 ; v1(3450,1275) 3491.73,1233.27 U6_15.36@3491.73,1180 ; v1(3450,1825) 3491.73,1783.27 U6_14.36@3491.73,1730 ; v1(3450,2375) 3491.73,2333.27 U6_13.36@3491.73,2280 ; v1(3450,2925) 3491.73,2883.27 U6_12.36@3491.73,2830 ; v1(3450,3475) 3491.73,3433.27 U6_11.36@3491.73,3380 ; v1(3450,4025) 3491.73,3983.27 U6_10.36@3491.73,3930 ; v1(3450,4575) 3491.73,4533.27 U6_9.36@3491.73,4480 ; v1(3450,5125) 3491.73,5083.27 U6_8.36@3491.73,5030 ; v1(3450,5675) 3491.73,5633.27 U6_7.36@3491.73,5580 ; v1(3450,6225) 3491.73,6183.27 U6_6.36@3491.73,6130 ; v1(3450,6775) 3491.73,6733.27 U6_5.36@3491.73,6680 ; v1(3450,7325) 3491.73,7283.27 U6_4.36@3491.73,7230 ; v1(3450,7875) 3491.73,7833.27 U6_3.36@3491.73,7780 ; v1(3450,8425) 3491.73,8383.27 U6_2.36@3491.73,8330 ; v1(3450,8975) 3491.73,8933.27 U6_1.36@3491.73,8880 ; U6_16.2@3511.42,320 U6_16.4@3550.79,320 ; U6_15.2@3511.42,870 U6_15.4@3550.79,870 ; U6_14.2@3511.42,1420 U6_14.4@3550.79,1420 ; U6_13.2@3511.42,1970 U6_13.4@3550.79,1970 ; U6_12.2@3511.42,2520 U6_12.4@3550.79,2520 ; U6_11.2@3511.42,3070 U6_11.4@3550.79,3070 ; U6_10.2@3511.42,3620 U6_10.4@3550.79,3620 ; U6_9.2@3511.42,4170 U6_9.4@3550.79,4170 ; U6_8.2@3511.42,4720 U6_8.4@3550.79,4720 ; U6_7.2@3511.42,5270 U6_7.4@3550.79,5270 ; U6_6.2@3511.42,5820 U6_6.4@3550.79,5820 ; U6_5.2@3511.42,6370 U6_5.4@3550.79,6370 ; U6_4.2@3511.42,6920 U6_4.4@3550.79,6920 ; U6_3.2@3511.42,7470 U6_3.4@3550.79,7470 ; U6_2.2@3511.42,8020 U6_2.4@3550.79,8020 ; U6_1.2@3511.42,8570 U6_1.4@3550.79,8570 ; U6_16.3@3531.1,320 3531.1,248.9 3550,230 3590.94,230 3609.84,248.9 U6_16.7@3609.84,320 U6_16.6@3590.16,320 ; U6_15.3@3531.1,870 3531.1,798.9 3550,780 3590.94,780 3609.84,798.9 U6_15.7@3609.84,870 U6_15.6@3590.16,870 ; U6_14.3@3531.1,1420 3531.1,1348.9 3550,1330 3590.94,1330 3609.84,1348.9 U6_14.7@3609.84,1420 U6_14.6@3590.16,1420 ; U6_13.3@3531.1,1970 3531.1,1898.9 3550,1880 3590.94,1880 3609.84,1898.9 U6_13.7@3609.84,1970 U6_13.6@3590.16,1970 ; U6_12.3@3531.1,2520 3531.1,2448.9 3550,2430 3590.94,2430 3609.84,2448.9 U6_12.7@3609.84,2520 U6_12.6@3590.16,2520 ; U6_11.3@3531.1,3070 3531.1,2998.9 3550,2980 3590.94,2980 3609.84,2998.9 U6_11.7@3609.84,3070 U6_11.6@3590.16,3070 ; U6_10.3@3531.1,3620 3531.1,3548.9 3550,3530 3590.94,3530 3609.84,3548.9 U6_10.7@3609.84,3620 U6_10.6@3590.16,3620 ; U6_9.3@3531.1,4170 3531.1,4098.9 3550,4080 3590.94,4080 3609.84,4098.9 U6_9.7@3609.84,4170 U6_9.6@3590.16,4170 ; U6_8.3@3531.1,4720 3531.1,4648.9 3550,4630 3590.94,4630 3609.84,4648.9 U6_8.7@3609.84,4720 U6_8.6@3590.16,4720 ; U6_7.3@3531.1,5270 3531.1,5198.9 3550,5180 3590.94,5180 3609.84,5198.9 U6_7.7@3609.84,5270 U6_7.6@3590.16,5270 ; U6_6.3@3531.1,5820 3531.1,5748.9 3550,5730 3590.94,5730 3609.84,5748.9 U6_6.7@3609.84,5820 U6_6.6@3590.16,5820 ; U6_5.3@3531.1,6370 3531.1,6298.9 3550,6280 3590.94,6280 3609.84,6298.9 U6_5.7@3609.84,6370 U6_5.6@3590.16,6370 ; U6_4.3@3531.1,6920 3531.1,6848.9 3550,6830 3590.94,6830 3609.84,6848.9 U6_4.7@3609.84,6920 U6_4.6@3590.16,6920 ; U6_3.3@3531.1,7470 3531.1,7398.9 3550,7380 3590.94,7380 3609.84,7398.9 U6_3.7@3609.84,7470 U6_3.6@3590.16,7470 ; U6_2.3@3531.1,8020 3531.1,7948.9 3550,7930 3590.94,7930 3609.84,7948.9 U6_2.7@3609.84,8020 U6_2.6@3590.16,8020 ; U6_1.3@3531.1,8570 3531.1,8498.9 3550,8480 3590.94,8480 3609.84,8498.9 U6_1.7@3609.84,8570 U6_1.6@3590.16,8570 ; v1(3609.84,260.16) 3735.16,260.16 3755,280 U6_16.13@3755,366.73 ; U6_16.30@3609.84,630 v1@3609.84,689.84 ; v1(3609.84,810.16) 3735.16,810.16 3755,830 U6_15.13@3755,916.73 ; U6_15.30@3609.84,1180 v1@3609.84,1239.84 ; v1(3609.84,1360.16) 3735.16,1360.16 3755,1380 U6_14.13@3755,1466.73 ; U6_14.30@3609.84,1730 v1@3609.84,1789.84 ; v1(3609.84,1910.16) 3735.16,1910.16 3755,1930 U6_13.13@3755,2016.73 ; U6_13.30@3609.84,2280 v1@3609.84,2339.84 ; v1(3609.84,2460.16) 3735.16,2460.16 3755,2480 U6_12.13@3755,2566.73 ; U6_12.30@3609.84,2830 v1@3609.84,2889.84 ; v1(3609.84,3010.16) 3735.16,3010.16 3755,3030 U6_11.13@3755,3116.73 ; U6_11.30@3609.84,3380 v1@3609.84,3439.84 ; v1(3609.84,3560.16) 3735.16,3560.16 3755,3580 U6_10.13@3755,3666.73 ; U6_10.30@3609.84,3930 v1@3609.84,3989.84 ; v1(3609.84,4110.16) 3735.16,4110.16 3755,4130 U6_9.13@3755,4216.73 ; U6_9.30@3609.84,4480 v1@3609.84,4539.84 ; v1(3609.84,4660.16) 3735.16,4660.16 3755,4680 U6_8.13@3755,4766.73 ; U6_8.30@3609.84,5030 v1@3609.84,5089.84 ; v1(3609.84,5210.16) 3735.16,5210.16 3755,5230 U6_7.13@3755,5316.73 ; U6_7.30@3609.84,5580 v1@3609.84,5639.84 ; v1(3609.84,5760.16) 3735.16,5760.16 3755,5780 U6_6.13@3755,5866.73 ; U6_6.30@3609.84,6130 v1@3609.84,6189.84 ; v1(3609.84,6310.16) 3735.16,6310.16 3755,6330 U6_5.13@3755,6416.73 ; U6_5.30@3609.84,6680 v1@3609.84,6739.84 ; v1(3609.84,6860.16) 3735.16,6860.16 3755,6880 U6_4.13@3755,6966.73 ; U6_4.30@3609.84,7230 v1@3609.84,7289.84 ; v1(3609.84,7410.16) 3735.16,7410.16 3755,7430 U6_3.13@3755,7516.73 ; U6_3.30@3609.84,7780 v1@3609.84,7839.84 ; v1(3609.84,7960.16) 3735.16,7960.16 3755,7980 U6_2.13@3755,8066.73 ; U6_2.30@3609.84,8330 v1@3609.84,8389.84 ; v1(3609.84,8510.16) 3735.16,8510.16 3755,8530 U6_1.13@3755,8616.73 ; U6_1.30@3609.84,8880 v1@3609.84,8939.84
  TopLayer w20: v1(8968.07,7912.4) D4.1@9030.71,7912.4 ; R43.1@9112.4,7250 9270,7250 9300,7280 Q2.3@9300,7400
  BottomLayer w20: C13_16.2@3369.88,550 3411.61,508.27 C15_16.2@3411.61,400 3395,400 v1(3370,425) ; C13_15.2@3369.88,1100 3411.61,1058.27 C15_15.2@3411.61,950 3395,950 v1(3370,975) ; C13_14.2@3369.88,1650 3411.61,1608.27 C15_14.2@3411.61,1500 3395,1500 v1(3370,1525) ; C13_13.2@3369.88,2200 3411.61,2158.27 C15_13.2@3411.61,2050 3395,2050 v1(3370,2075) ; C13_12.2@3369.88,2750 3411.61,2708.27 C15_12.2@3411.61,2600 3395,2600 v1(3370,2625) ; C13_11.2@3369.88,3300 3411.61,3258.27 C15_11.2@3411.61,3150 3395,3150 v1(3370,3175) ; C13_10.2@3369.88,3850 3411.61,3808.27 C15_10.2@3411.61,3700 3395,3700 v1(3370,3725) ; C13_9.2@3369.88,4400 3411.61,4358.27 C15_9.2@3411.61,4250 3395,4250 v1(3370,4275) ; C13_8.2@3369.88,4950 3411.61,4908.27 C15_8.2@3411.61,4800 3395,4800 v1(3370,4825) ; C13_7.2@3369.88,5500 3411.61,5458.27 C15_7.2@3411.61,5350 3395,5350 v1(3370,5375) ; C13_6.2@3369.88,6050 3411.61,6008.27 C15_6.2@3411.61,5900 3395,5900 v1(3370,5925) ; C13_5.2@3369.88,6600 3411.61,6558.27 C15_5.2@3411.61,6450 3395,6450 v1(3370,6475) ; C13_4.2@3369.88,7150 3411.61,7108.27 C15_4.2@3411.61,7000 3395,7000 v1(3370,7025) ; C13_3.2@3369.88,7700 3411.61,7658.27 C15_3.2@3411.61,7550 3395,7550 v1(3370,7575) ; C13_2.2@3369.88,8250 3411.61,8208.27 C15_2.2@3411.61,8100 3395,8100 v1(3370,8125) ; C13_1.2@3369.88,8800 3411.61,8758.27 C15_1.2@3411.61,8650 3395,8650 v1(3370,8675) ; R8_16.2@3577.6,625 3610,657.4 v1(3610,690) ; R8_15.2@3577.6,1175 3610,1207.4 v1(3610,1240) ; R8_14.2@3577.6,1725 3610,1757.4 v1(3610,1790) ; R8_13.2@3577.6,2275 3610,2307.4 v1(3610,2340) ; R8_12.2@3577.6,2825 3610,2857.4 v1(3610,2890) ; R8_11.2@3577.6,3375 3610,3407.4 v1(3610,3440) ; R8_10.2@3577.6,3925 3610,3957.4 v1(3610,3990) ; R8_9.2@3577.6,4475 3610,4507.4 v1(3610,4540) ; R8_8.2@3577.6,5025 3610,5057.4 v1(3610,5090) ; R8_7.2@3577.6,5575 3610,5607.4 v1(3610,5640) ; R8_6.2@3577.6,6125 3610,6157.4 v1(3610,6190) ; R8_5.2@3577.6,6675 3610,6707.4 v1(3610,6740) ; R8_4.2@3577.6,7225 3610,7257.4 v1(3610,7290) ; R8_3.2@3577.6,7775 3610,7807.4 v1(3610,7840) ; R8_2.2@3577.6,8325 3610,8357.4 v1(3610,8390) ; R8_1.2@3577.6,8875 3610,8907.4 v1(3610,8940) ; Q2.3@9300,7400 R39.2@9387.6,7400
+5VR: D6.1 Q5.3 R28.1 R36.2 R48.2 R49.2 TP3.1 U18.3 U19.3 | length 978
  TopLayer w20: R28.1@7900,7612.4 v1(7900,7655) ; R48.2@8100,5937.6 v1(8387.6,5937.6) 8500,6050 Q5.3@8500,6156.5 ; D6.1@8312.6,6205.71 8358.86,6159.45 Q5.3@8502.95,6159.45 ; v1(8840,4750) R36.2@8887.6,4750 ; v1(9075,6085) U19.3@9075,6147.64 ; v1(9075,7335) U18.3@9075,7397.64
